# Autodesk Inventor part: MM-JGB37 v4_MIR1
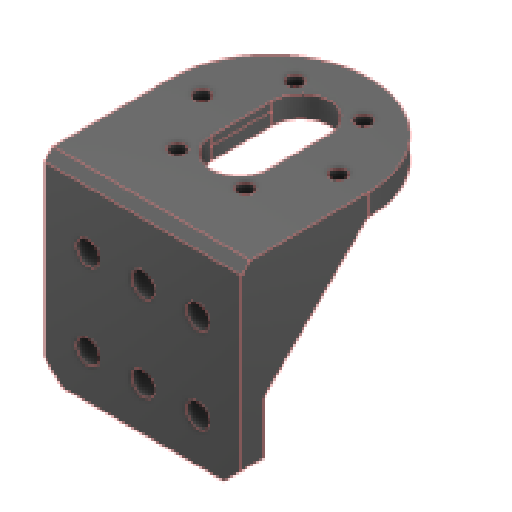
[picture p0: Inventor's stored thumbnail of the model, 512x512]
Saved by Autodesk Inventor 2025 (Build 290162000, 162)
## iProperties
Created: 2024-01
Part Number: MM-JGB37 v4_MIR1
Material: Plastica PET
Document SubType Name: Modeling
Designer: R5800u
Density: 1.541 g/cm^3
Appearance: Rosso
Sending System: Autodesk Translation Framework v12.14.0.127
Preprocessor: ST-DEVELOPER v20
Title: MM-JGB37 v4.step
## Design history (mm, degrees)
derived "MM-JGB37 v4.ipt"
  sketch "Schizzo1"
    geometry: L1 (0, -42.5)-(0, 0) reference; L2 (-40, -42.5)-(0, -42.5) reference; L3 (-40, -42.5)-(-40, 0) reference; L4 (0, 0)-(-40, 0) reference; 1 further point
  sketch "Schizzo6"
    geometry: L1 (2.5, -5)-(2.5, 24) reference; L2 (-42.5, 24)-(-42.5, -5) reference; L3 (2.5, -5)-(-42.5, -5) reference; L4 (-42.5, -5)-(-42.5, 0) reference; L5 (-42.5, 0)-(2.5, 0) reference; L6 (2.5, 0)-(2.5, -5) reference; L7 (0, 0)-(-40, 0) reference; L8 (0, -5)-(0, 0) reference; L9 (-40, -5)-(0, -5) reference; L10 (-40, -5)-(-40, 0) reference; 1 further point
  sketch "Schizzo7"
    geometry: L1 (-5, -5)-(-29, -5) reference; L2 (-29, 0)-(-29, -5) reference; L3 (0, 0)-(-29, 0) reference; L4 (0, 0)-(0, -44.5) reference; L5 (-5, -44.5)-(0, -44.5) reference; L6 (-5, -44.5)-(-5, -5) reference; L7 (-27.973, -5.631)-(-5, -28.604) reference; A1 r 1.151 centre (-29, -6.151) between (-27.973, -5.631) and (-29, -5) reference; 1 further point
  sketch "Schizzo8"
    geometry: L1 (-10, -180.5)-(-10, 19.5) reference; L2 (0, 29.5)-(-300, 29.5) reference; L3 (-45, 0)-(0, 0) reference; L4 (-45, 0)-(-45, 15.067) reference; L5 (0, 16.481)-(0, 38.869) reference; L6 (0, 0)-(0, 15.067) reference; 8 further points
  node "Piano di lavoro1"
feature "Solido1::MM-JGB37 v4.ipt" dims "d0" = 10
tag "Lavorazione contrassegno1"
sketch "Schizzo3"
  geometry: L1 (-20, 0)-(-20, 29) reference; L2 (20, 29)-(-20, 29) reference; L3 (20, 29)-(20, 0) reference; L4 (6.5, -7)-(6.5, 7) reference; L5 (-6.5, 7)-(-6.5, -7) reference; C1 r 1.75 at (-15.5, 0) reference; C2 r 1.75 at (7.75, -13.423) reference; C3 r 1.75 at (-7.75, -13.423) reference; C4 r 1.75 at (-7.75, 13.423) reference; C5 r 1.75 at (15.5, 0) reference; C6 r 1.75 at (7.75, 13.423) reference; A1 r 20 centre (0, 0) between (-20, 0) and (20, 0) reference; A2 r 6.5 centre (0, 7) between (6.5, 7) and (-6.5, 7) reference; A3 r 6.5 centre (0, -7) between (-6.5, -7) and (6.5, -7) reference; 1 further point
sketch "Schizzo5"
  geometry: L1 (-20, 0)-(-20, 29) reference; L2 (-20, 29)-(20, 29) reference; L3 (20, 29)-(20, 0) reference; L4 (-6.5, 7)-(-6.5, -7) reference; L5 (6.5, -7)-(6.5, 7) reference; L6 (22.5, 0)-(22.5, 31.5) reference; L7 (22.5, 31.5)-(-22.5, 31.5) reference; L8 (-22.5, 31.5)-(-22.5, 0) reference; L9 (-22.5, 29)-(-20, 29) reference; L10 (22.5, 29)-(20, 29) reference; C1 r 1.75 at (7.75, 13.423) reference; C2 r 1.75 at (15.5, 0) reference; C3 r 1.75 at (-7.75, 13.423) reference; C4 r 1.75 at (-7.75, -13.423) reference; C5 r 1.75 at (7.75, -13.423) reference; C6 r 1.75 at (-15.5, 0) reference; A1 r 20 centre (0, 0) between (-20, 0) and (20, 0) reference; A2 r 6.5 centre (0, -7) between (-6.5, -7) and (6.5, -7) reference; A3 r 6.5 centre (0, 7) between (6.5, 7) and (-6.5, 7) reference; A4 r 22.5 centre (0, 0) between (-22.5, 0) and (22.5, 0) reference; 1 further point
node "Solido1"
